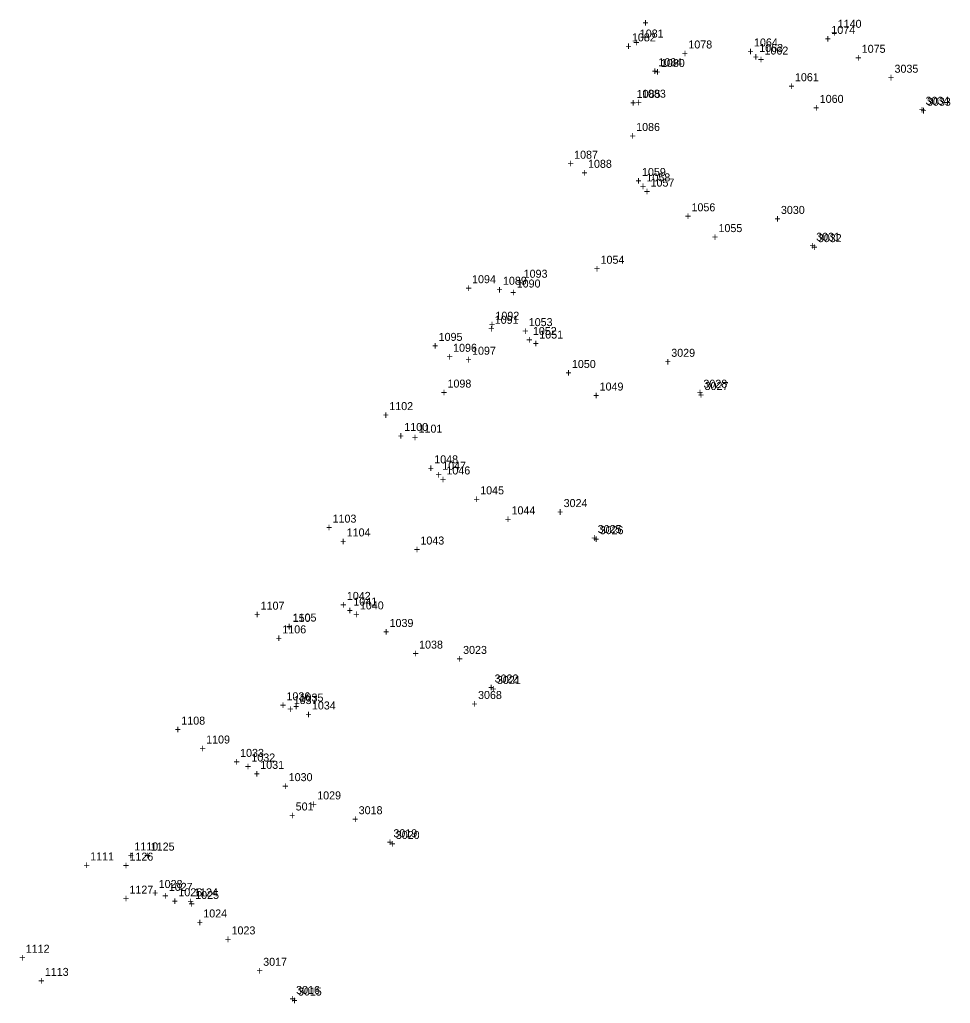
# Model space of a CAD drawing. Extents: x 1667192 to 1669644, y 336680 to 339991.
# Drawn here: x 1667533.8 to 1667824.5, y 338666.6 to 338973.9 of the extents above; entities that cross this region are included whole.
import ezdxf

# ---------------------------------------------------------------- set-up
doc = ezdxf.new("R2010")
doc.units = 0
for name, color, linetype in [('S_Control_Temp_Traverse', 7, 'Continuous'), ('S_Control_Traverse_Point', 7, 'Continuous'), ('S_Curb_Type_5', 7, 'Continuous'), ('S_Drainage_CB', 7, 'Continuous'), ('S_Drainage_Ditch_Line', 7, 'Continuous'), ('S_Ground_Elevation', 7, 'Continuous'), ('S_Misc_MiscItems', 7, 'Continuous'), ('S_Roadway_Centerline', 7, 'Continuous'), ('S_Roadway_Edge_Pavement', 7, 'Continuous'), ('S_Roadway_Edge_TW', 7, 'Continuous'), ('S_Traffic_Sign_DoublePost', 7, 'Continuous'), ('S_Traffic_Sign_SinglePost', 7, 'Continuous'), ('S_Trees_TreeLine', 7, 'Continuous'), ('S_Utilities_GuyWire3', 7, 'Continuous'), ('S_Utilities_Pole_Power', 7, 'Continuous'), ('S_Utilities_Pole_StreetLight', 7, 'Continuous'), ('S_Utilities_UG_Electrical_Line', 7, 'Continuous')]:
    doc.layers.add(name, color=color, linetype=linetype)

msp = doc.modelspace()

# ---------------------------------------------------------------- texts
at = {"layer": 'S_Control_Temp_Traverse'}
for s, p in [('150', (1667619.12, 338785.73)), ('+', (1667617.06, 338782.98))]:
    msp.add_text(s, height=2.5, dxfattribs=at).set_placement(p)
at = {"layer": 'S_Control_Traverse_Point'}
for s, p in [('501', (1667620.03, 338726.82)), ('501', (1667620.03, 338726.82)), ('501', (1667620.03, 338726.82)), ('501', (1667620.03, 338726.82)), ('501', (1667620.03, 338726.82)), ('501', (1667620.03, 338726.82)), ('501', (1667620.03, 338726.82)), ('501', (1667620.03, 338726.82)), ('501', (1667620.03, 338726.82)), ('501', (1667620.03, 338726.82)), ('+', (1667617.97, 338724.07)), ('+', (1667617.97, 338724.07)), ('+', (1667617.97, 338724.07)), ('+', (1667617.97, 338724.07)), ('+', (1667617.97, 338724.07)), ('+', (1667617.97, 338724.07)), ('+', (1667617.97, 338724.07)), ('+', (1667617.97, 338724.07)), ('+', (1667617.97, 338724.07)), ('+', (1667617.97, 338724.07))]:
    msp.add_text(s, height=2.5, dxfattribs=at).set_placement(p)
at = {"layer": 'S_Curb_Type_5'}
for s, p in [('3033', (1667817.21, 338947)), ('+', (1667815.15, 338944.25)), ('3032', (1667783.11, 338904.38)), ('+', (1667781.05, 338901.63)), ('3027', (1667747.75, 338858.18)), ('+', (1667745.68, 338855.43)), ('3026', (1667714.98, 338813.14)), ('+', (1667712.91, 338810.39)), ('3021', (1667682.88, 338766.32)), ('+', (1667680.82, 338763.57)), ('3020', (1667651.29, 338717.92)), ('+', (1667649.23, 338715.17)), ('3015', (1667620.73, 338669)), ('+', (1667618.67, 338666.25))]:
    msp.add_text(s, height=2.5, dxfattribs=at).set_placement(p)
at = {"layer": 'S_Drainage_CB'}
for s, p in [('3068', (1667676.99, 338761.65)), ('+', (1667674.92, 338758.9))]:
    msp.add_text(s, height=2.5, dxfattribs=at).set_placement(p)
at = {"layer": 'S_Drainage_Ditch_Line'}
for s, p in [('1063', (1667764.83, 338963.79)), ('+', (1667762.77, 338961.04)), ('1058', (1667729.58, 338923.36)), ('+', (1667727.52, 338920.61)), ('1052', (1667694.11, 338875.38)), ('+', (1667692.05, 338872.63)), ('1047', (1667665.79, 338833.27)), ('+', (1667663.73, 338830.52)), ('1041', (1667638.04, 338790.83)), ('+', (1667635.98, 338788.08)), ('1036', (1667617.15, 338761.25)), ('+', (1667615.09, 338758.5)), ('1032', (1667606.19, 338742.11)), ('+', (1667604.13, 338739.36)), ('1027', (1667580.39, 338701.7)), ('+', (1667578.33, 338698.95))]:
    msp.add_text(s, height=2.5, dxfattribs=at).set_placement(p)
at = {"layer": 'S_Ground_Elevation'}
for s, p in [('+', (1667728.32, 338971.67)), ('1078', (1667742.68, 338964.89)), ('1064', (1667763.18, 338965.52)), ('1062', (1667766.46, 338962.99)), ('+', (1667740.62, 338962.14)), ('+', (1667761.12, 338962.77)), ('+', (1667764.4, 338960.24)), ('1088', (1667711.34, 338927.6)), ('+', (1667709.28, 338924.85)), ('1059', (1667728.2, 338925.06)), ('+', (1667726.14, 338922.31)), ('1057', (1667730.87, 338921.73)), ('+', (1667728.81, 338918.98)), ('1089', (1667684.77, 338891.07)), ('+', (1667682.7, 338888.32)), ('1053', (1667692.82, 338878.15)), ('+', (1667690.76, 338875.4)), ('1051', (1667696.12, 338874.25)), ('+', (1667694.05, 338871.5)), ('1096', (1667669.2, 338870.13)), ('+', (1667667.14, 338867.38)), ('1100', (1667653.94, 338845.38)), ('+', (1667651.88, 338842.63)), ('1048', (1667663.31, 338835.27)), ('+', (1667661.25, 338832.52)), ('1046', (1667667.11, 338831.8)), ('+', (1667665.05, 338829.05)), ('1104', (1667635.96, 338812.44)), ('+', (1667633.89, 338809.69)), ('1042', (1667636.01, 338792.61)), ('+', (1667633.95, 338789.86)), ('1040', (1667640.08, 338789.64)), ('+', (1667638.02, 338786.89)), ('1106', (1667615.86, 338782.15)), ('+', (1667613.8, 338779.4)), ('1037', (1667619.42, 338760.06)), ('+', (1667617.36, 338757.31)), ('1109', (1667592.06, 338747.74)), ('+', (1667590, 338745)), ('1033', (1667602.67, 338743.56)), ('+', (1667600.61, 338740.81)), ('1031', (1667608.97, 338739.82)), ('+', (1667606.91, 338737.07)), ('1110', (1667569.63, 338714.33)), ('+', (1667567.57, 338711.58)), ('1028', (1667577.24, 338702.6)), ('+', (1667575.17, 338699.85)), ('1026', (1667583.38, 338700.01)), ('+', (1667581.32, 338697.26)), ('1113', (1667541.68, 338675.14)), ('+', (1667539.62, 338672.39))]:
    msp.add_text(s, height=2.5, dxfattribs=at).set_placement(p)
at = {"layer": 'S_Misc_MiscItems'}
for s, p in [('1083', (1667728.21, 338949.52)), ('+', (1667726.15, 338946.77))]:
    msp.add_text(s, height=2.5, dxfattribs=at).set_placement(p)
at = {"layer": 'S_Roadway_Centerline'}
for s, p in [('3035', (1667807.07, 338957.31)), ('+', (1667805.01, 338954.56)), ('3030', (1667771.59, 338913.2)), ('+', (1667769.53, 338910.45)), ('3029', (1667737.34, 338868.56)), ('+', (1667735.28, 338865.81)), ('3024', (1667703.73, 338821.61)), ('+', (1667701.67, 338818.86)), ('3023', (1667672.32, 338775.73)), ('+', (1667670.26, 338772.98)), ('3018', (1667639.71, 338725.65)), ('+', (1667637.65, 338722.9)), ('3017', (1667609.88, 338678.29)), ('+', (1667607.82, 338675.54))]:
    msp.add_text(s, height=2.5, dxfattribs=at).set_placement(p)
at = {"layer": 'S_Roadway_Edge_Pavement'}
for s, p in [('1074', (1667787.34, 338969.44)), ('1140', (1667789.33, 338971.35)), ('+', (1667785.28, 338966.69)), ('+', (1667787.27, 338968.6)), ('1061', (1667775.97, 338954.66)), ('+', (1667773.9, 338951.91)), ('3034', (1667816.76, 338947.3)), ('+', (1667814.7, 338944.55)), ('1056', (1667743.66, 338914.02)), ('+', (1667741.6, 338911.27)), ('3031', (1667782.6, 338904.81)), ('+', (1667780.54, 338902.06)), ('1050', (1667706.31, 338865.07)), ('+', (1667704.25, 338862.32)), ('3028', (1667747.37, 338858.9)), ('+', (1667745.31, 338856.15)), ('1045', (1667677.66, 338825.59)), ('+', (1667675.6, 338822.84)), ('3025', (1667714.36, 338813.49)), ('+', (1667712.3, 338810.74)), ('1039', (1667649.36, 338784.15)), ('+', (1667647.3, 338781.4)), ('3022', (1667682.17, 338766.8)), ('+', (1667680.11, 338764.05)), ('1030', (1667617.85, 338735.98)), ('+', (1667615.79, 338733.23)), ('3019', (1667650.55, 338718.46)), ('+', (1667648.49, 338715.71)), ('1024', (1667591.17, 338693.4)), ('+', (1667589.11, 338690.65)), ('3016', (1667620.16, 338669.49)), ('+', (1667618.1, 338666.74))]:
    msp.add_text(s, height=2.5, dxfattribs=at).set_placement(p)
at = {"layer": 'S_Roadway_Edge_TW'}
for s, p in [('1075', (1667796.83, 338963.53)), ('+', (1667794.77, 338960.78)), ('1060', (1667783.71, 338947.89)), ('+', (1667781.64, 338945.14)), ('1055', (1667752.09, 338907.52)), ('+', (1667750.03, 338904.77)), ('1049', (1667714.96, 338858.02)), ('+', (1667712.9, 338855.27)), ('1044', (1667687.45, 338819.33)), ('+', (1667685.39, 338816.58)), ('1038', (1667658.58, 338777.39)), ('+', (1667656.52, 338774.64)), ('1029', (1667626.75, 338730.28)), ('+', (1667624.69, 338727.53)), ('1023', (1667600, 338688.1)), ('+', (1667597.94, 338685.35))]:
    msp.add_text(s, height=2.5, dxfattribs=at).set_placement(p)
at = {"layer": 'S_Traffic_Sign_DoublePost'}
for s, p in [('1035', (1667621.25, 338760.84)), ('+', (1667619.19, 338758.09)), ('1034', (1667625.1, 338758.38)), ('+', (1667623.04, 338755.63))]:
    msp.add_text(s, height=2.5, dxfattribs=at).set_placement(p)
at = {"layer": 'S_Traffic_Sign_SinglePost'}
for s, p in [('1054', (1667715.25, 338897.63)), ('+', (1667713.19, 338894.88))]:
    msp.add_text(s, height=2.5, dxfattribs=at).set_placement(p)
at = {"layer": 'S_Trees_TreeLine'}
for s, p in [('1087', (1667707, 338930.45)), ('+', (1667704.94, 338927.7)), ('1094', (1667675.12, 338891.55)), ('+', (1667673.06, 338888.8)), ('1095', (1667664.68, 338873.53)), ('+', (1667662.62, 338870.78)), ('1102', (1667649.27, 338851.9)), ('+', (1667647.2, 338849.15)), ('1103', (1667631.55, 338816.75)), ('+', (1667629.49, 338814)), ('1107', (1667609.09, 338789.55)), ('+', (1667607.03, 338786.8)), ('1108', (1667584.31, 338753.64)), ('+', (1667582.25, 338750.89)), ('1111', (1667555.84, 338711.23)), ('+', (1667553.78, 338708.48)), ('1112', (1667535.72, 338682.37)), ('+', (1667533.65, 338679.62))]:
    msp.add_text(s, height=2.5, dxfattribs=at).set_placement(p)
at = {"layer": 'S_Utilities_GuyWire3'}
for s, p in [('1082', (1667725.05, 338967.11)), ('1081', (1667727.51, 338968.31)), ('+', (1667722.99, 338964.36)), ('+', (1667725.45, 338965.56)), ('1093', (1667691.24, 338893.26)), ('+', (1667689.18, 338890.51)), ('1091', (1667682.2, 338878.87)), ('+', (1667680.14, 338876.12)), ('1125', (1667574.76, 338714.29)), ('1126', (1667568.12, 338711.15)), ('+', (1667572.7, 338711.54)), ('+', (1667566.06, 338708.4)), ('1127', (1667568.1, 338700.83)), ('+', (1667566.04, 338698.08))]:
    msp.add_text(s, height=2.5, dxfattribs=at).set_placement(p)
at = {"layer": 'S_Utilities_Pole_Power'}
for s, p in [('1080', (1667734.11, 338959.1)), ('+', (1667732.05, 338956.35)), ('1090', (1667689.06, 338890.2)), ('+', (1667687, 338887.45)), ('1092', (1667682.42, 338880.14)), ('+', (1667680.36, 338877.39)), ('1097', (1667675.12, 338869.21)), ('+', (1667673.05, 338866.46)), ('1098', (1667667.45, 338858.94)), ('+', (1667665.39, 338856.19)), ('1101', (1667658.4, 338844.86)), ('+', (1667656.34, 338842.11)), ('1105', (1667619.08, 338785.85)), ('+', (1667617.02, 338783.1)), ('1124', (1667588.29, 338699.97)), ('1025', (1667588.64, 338699.17)), ('+', (1667586.23, 338697.22)), ('+', (1667586.58, 338696.42))]:
    msp.add_text(s, height=2.5, dxfattribs=at).set_placement(p)
at = {"layer": 'S_Utilities_Pole_StreetLight'}
for s, p in [('1043', (1667658.99, 338809.91)), ('+', (1667656.93, 338807.16))]:
    msp.add_text(s, height=2.5, dxfattribs=at).set_placement(p)
at = {"layer": 'S_Utilities_UG_Electrical_Line'}
for s, p in [('1084', (1667733.3, 338959.34)), ('+', (1667731.23, 338956.59)), ('1085', (1667726.53, 338949.45)), ('+', (1667724.47, 338946.7)), ('1086', (1667726.37, 338939.11)), ('+', (1667724.31, 338936.36))]:
    msp.add_text(s, height=2.5, dxfattribs=at).set_placement(p)

doc.saveas('drawing.dxf')
